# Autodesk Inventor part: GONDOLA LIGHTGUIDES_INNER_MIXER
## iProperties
Shininess: 64.0
Length Units: 11272
Angle Units: 11279
Time Units: 11290
Mass Units: 11286
Length Display Precision: 3
Angle Display Precision: 2
Compacted: True
Part Number: GONDOLA LIGHTGUIDES_INNER_MIXER
Document SubType Name: Modeling
Created: 2004-08
Designer: John Blackburn
Manufacturer: Standard
Standards Organization: Custom
Material: Lexan, Clear
Density: 0.0
Volumn: 0.0
Area: 0.0
PropertySet Name: Model Information
Control State: 0
Master: False
Checked Out: False
Author: John Blackburn
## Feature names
1. Base1
